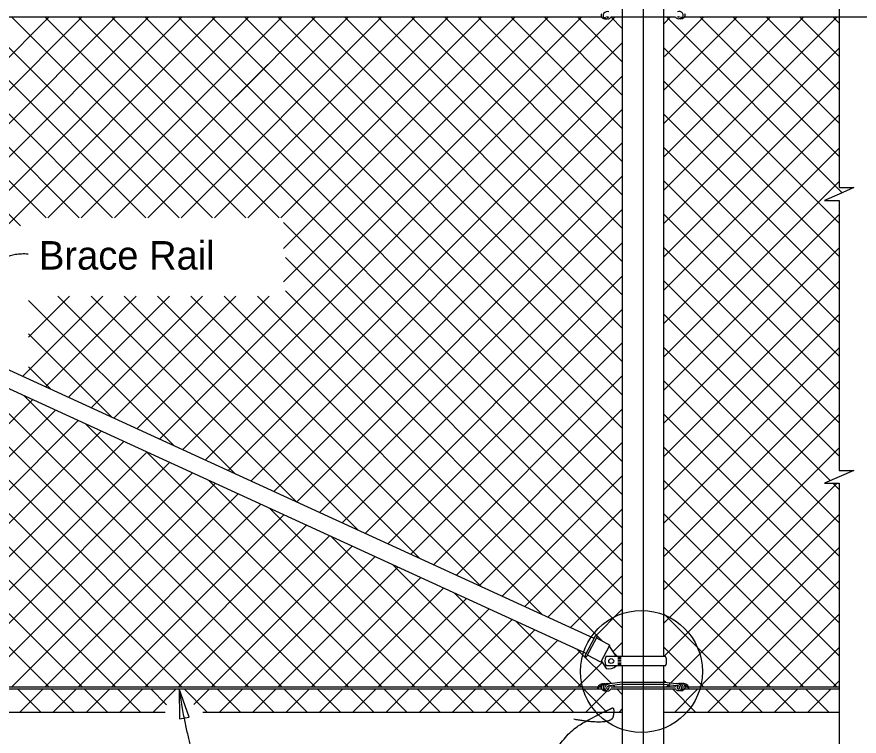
# Model space of a CAD drawing. Extents: x 0 to 41.1, y 0 to 26.4.
# Drawn here: x 17.77 to 23.73, y 17.3 to 22.39 of the extents above; entities that cross this region are included whole.
import ezdxf

# ---------------------------------------------------------------- set-up
doc = ezdxf.new("R2010")
doc.units = 0
for name, color, linetype in [('CL_Major', 7, 'Continuous'), ('Dimension', 7, 'Continuous'), ('Miscellaneous', 7, 'Continuous'), ('SteelMisc', 7, 'Continuous'), ('SteelMisc_h', 7, 'Continuous'), ('SupstrConc', 7, 'Continuous'), ('TextStructures', 7, 'Continuous')]:
    doc.layers.add(name, color=color, linetype=linetype)

msp = doc.modelspace()

# ---------------------------------------------------------------- linework, layer by layer
at = {"layer": 'CL_Major'}
msp.add_line((22.2062, 25.6784), (22.2062, 14.8312), dxfattribs=at)
at = {"layer": 'Dimension'}
for points in [[(23.5932, 24.349), (23.5932, 21.1819), (23.6966, 21.1819), (23.5932, 21.1369), (23.4899, 21.0919), (23.5932, 21.0919), (23.5932, 20.1983)], [(23.5932, 20.1983), (23.5932, 19.1806), (23.6966, 19.1806), (23.5932, 19.1356), (23.4899, 19.0906), (23.5932, 19.0906), (23.5932, 16.8862)]]:
    msp.add_lwpolyline(points, dxfattribs=at)
msp.add_lwpolyline([(18.9209, 17.6338), (18.9225, 17.4226), (18.992, 17.4349)], close=True, dxfattribs=at)
msp.add_circle((22.1934, 17.7574), 0.4318, dxfattribs=at)
for points in [[(17.8509, 20.7118), (17.6943, 20.72), (17.5763, 20.5615), (17.5733, 20.4403), (17.578, 20.2726), (17.6407, 19.9238)], [(18.6095, 16.8868), (18.8324, 16.8833), (18.9173, 16.9222), (19.0482, 17.0709), (18.9633, 17.3684), (18.9208, 17.6337)], [(20.4632, 14.9843), (21.3717, 14.9643), (21.3652, 16.4454), (21.4405, 16.9433), (21.6515, 17.3204), (21.8903, 17.4554), (21.9647, 17.4872), (22.0043, 17.5089), (21.982, 17.3708), (21.7151, 17.4193)]]:
    msp.add_open_spline(points, degree=2, dxfattribs=at)
at = {"layer": 'Miscellaneous'}
for p, q in [((16.1953, 20.586), (17.9993, 22.39)), ((16.32, 22.39), (17.7983, 20.9117)), ((16.357, 20.5119), (18.235, 22.39)), ((16.5186, 20.4379), (18.4707, 22.39)), ((16.5557, 22.39), (17.9778, 20.9679)), ((16.6803, 20.3639), (18.7064, 22.39)), ((16.7914, 22.39), (18.2135, 20.9679)), ((16.8419, 20.2898), (18.9421, 22.39)), ((17.0271, 22.39), (18.4492, 20.9679)), ((17.2628, 22.39), (18.6849, 20.9679)), ((17.4985, 22.39), (18.9206, 20.9679)), ((17.679, 20.8912), (19.1778, 22.39)), ((17.7342, 22.39), (19.1563, 20.9679)), ((17.9699, 22.39), (19.392, 20.9679)), ((17.9914, 20.9679), (19.4135, 22.39)), ((18.2056, 22.39), (19.6277, 20.9679)), ((18.2272, 20.9679), (19.6492, 22.39)), ((18.4413, 22.39), (22.0604, 18.7709)), ((18.677, 22.39), (22.0604, 19.0066)), ((18.6986, 20.9679), (20.1206, 22.39)), ((18.7818, 19.4013), (21.7706, 22.39)), ((18.9127, 22.39), (22.0604, 19.2423)), ((18.9343, 20.9679), (20.3563, 22.39)), ((18.9435, 19.3272), (22.0063, 22.39)), ((19.1484, 22.39), (22.0604, 19.478)), ((19.17, 20.9679), (20.5921, 22.39)), ((19.3184, 21.8234), (19.8849, 22.39)), ((19.3841, 22.39), (22.0604, 19.7137)), ((19.4057, 20.9679), (20.8278, 22.39)), ((19.6198, 22.39), (22.0604, 19.9494)), ((19.6414, 20.9679), (21.0635, 22.39)), ((19.66, 20.7508), (21.2992, 22.39)), ((19.66, 20.5151), (21.5349, 22.39)), ((19.8555, 22.39), (22.0604, 20.1851)), ((20.0912, 22.39), (22.0604, 20.4208)), ((20.3269, 22.39), (22.0604, 20.6565)), ((20.5626, 22.39), (22.0604, 20.8922)), ((20.7983, 22.39), (22.0604, 21.1279)), ((21.034, 22.39), (22.0604, 21.3636)), ((21.2697, 22.39), (22.0604, 21.5993)), ((21.5054, 22.39), (22.0604, 21.835)), ((21.7411, 22.39), (22.0604, 22.0707)), ((21.9768, 22.39), (22.0604, 22.3064)), ((22.3521, 21.3996), (23.3424, 22.39)), ((22.3521, 21.6353), (23.1067, 22.39)), ((22.3521, 21.1639), (23.5781, 22.39)), ((22.3521, 21.871), (22.871, 22.39)), ((22.3521, 22.3424), (22.3996, 22.39)), ((22.3565, 22.1112), (22.6353, 22.39)), ((22.3702, 22.39), (23.6142, 21.146)), ((22.6059, 22.39), (23.5931, 21.4028)), ((22.8416, 22.39), (23.5931, 21.6385)), ((23.0773, 22.39), (23.5931, 21.8742)), ((23.313, 22.39), (23.5931, 22.1099)), ((23.5487, 22.39), (23.5931, 22.3456)), ((19.1051, 19.2532), (22.0604, 22.2084)), ((22.3521, 22.1725), (23.5931, 20.9314)), ((22.3521, 20.9282), (23.5931, 22.1693)), ((18.4629, 20.9679), (19.5478, 22.0528)), ((19.2668, 19.1791), (22.0604, 21.9727)), ((22.3521, 21.9368), (23.5931, 20.6957)), ((22.3521, 20.6925), (23.5931, 21.9336)), ((19.4285, 19.1051), (22.0604, 21.737)), ((22.3521, 21.701), (23.5931, 20.46)), ((22.3521, 20.4568), (23.5931, 21.6979)), ((19.5901, 19.0311), (22.0604, 21.5013)), ((22.3521, 21.4653), (23.5931, 20.2243)), ((22.3521, 20.2211), (23.5931, 21.4622)), ((19.7518, 18.957), (22.0604, 21.2656)), ((22.3521, 21.2296), (23.5931, 19.9886)), ((22.3521, 19.9854), (23.5931, 21.2265)), ((19.9134, 18.883), (22.0604, 21.0299)), ((22.3521, 20.9939), (23.5931, 19.7529)), ((19.66, 20.9356), (22.0604, 18.5352)), ((22.3521, 19.7497), (23.5931, 20.9908)), ((15.2134, 20.9039), (18.4687, 17.6486)), ((20.0751, 18.8089), (22.0604, 20.7942)), ((22.3521, 20.7582), (23.5931, 19.5171)), ((22.3521, 19.514), (23.5931, 20.7551)), ((15.6483, 20.7047), (18.7044, 17.6486)), ((19.6731, 20.6868), (22.0604, 18.2995)), ((20.2368, 18.7349), (22.0604, 20.5585)), ((22.3521, 20.5225), (23.5931, 19.2814)), ((22.3521, 19.2783), (23.5931, 20.5194)), ((16.0832, 20.5055), (18.9401, 17.6486)), ((17.8119, 19.8455), (18.3797, 20.4134)), ((17.8545, 20.1239), (18.144, 20.4134)), ((17.9735, 19.7715), (18.6154, 20.4134)), ((18.0609, 20.4134), (19.3191, 19.1552)), ((18.1352, 19.6975), (18.8511, 20.4134)), ((18.2966, 20.4134), (19.754, 18.956)), ((18.2969, 19.6234), (19.0868, 20.4134)), ((18.4585, 19.5494), (19.3225, 20.4134)), ((18.5323, 20.4134), (20.1889, 18.7568)), ((18.6202, 19.4753), (19.5582, 20.4134)), ((18.768, 20.4134), (20.6238, 18.5576)), ((19.0037, 20.4134), (21.0587, 18.3584)), ((19.2394, 20.4134), (21.4936, 18.1592)), ((19.4751, 20.4134), (21.9144, 17.9741)), ((19.6731, 20.4511), (22.0604, 18.0638)), ((17.8545, 20.3841), (18.8842, 19.3544)), ((16.5181, 20.3063), (19.1758, 17.6486)), ((20.3984, 18.6608), (22.0604, 20.3228)), ((22.3521, 20.2868), (23.5306, 19.1083)), ((22.3521, 19.0426), (23.5931, 20.2837)), ((16.953, 20.1071), (19.4115, 17.6486)), ((17.8545, 20.1484), (18.4493, 19.5536)), ((20.5601, 18.5868), (22.0604, 20.0871)), ((22.3521, 20.0511), (23.5931, 18.81)), ((22.3521, 18.8069), (23.5931, 20.048)), ((17.3879, 19.9079), (19.6472, 17.6486)), ((17.8545, 19.9127), (18.0144, 19.7528)), ((20.7217, 18.5127), (22.0604, 19.8514)), ((22.3521, 19.8154), (23.5931, 18.5743)), ((22.3521, 18.5712), (23.5931, 19.8123)), ((16.6339, 18.4318), (17.8831, 19.6811)), ((17.8228, 19.7087), (19.8829, 17.6486)), ((16.2952, 19.5864), (18.233, 17.6486)), ((16.6339, 18.1961), (18.0448, 19.607)), ((20.8834, 18.4387), (22.0604, 19.6157)), ((22.3521, 19.5797), (23.5931, 18.3386)), ((22.3521, 18.3355), (23.5931, 19.5766)), ((16.6339, 17.9604), (18.2064, 19.533)), ((18.2576, 19.5095), (20.1186, 17.6486)), ((16.5577, 17.6486), (18.3681, 19.4589)), ((16.2349, 19.4109), (17.9973, 17.6486)), ((16.7934, 17.6486), (18.5298, 19.3849)), ((21.045, 18.3647), (22.0604, 19.38)), ((22.3521, 19.344), (23.5931, 18.1029)), ((22.3521, 18.0998), (23.5931, 19.3409)), ((17.0291, 17.6486), (18.6914, 19.3109)), ((18.6925, 19.3103), (20.3543, 17.6486)), ((17.2648, 17.6486), (18.8531, 19.2368)), ((17.5005, 17.6486), (19.0147, 19.1628)), ((21.2067, 18.2906), (22.0604, 19.1443)), ((17.7362, 17.6486), (19.1764, 19.0887)), ((19.1274, 19.1111), (20.59, 17.6486)), ((22.3521, 19.1083), (23.5931, 17.8672)), ((22.3521, 17.8641), (23.5785, 19.0905)), ((23.5484, 19.0905), (23.5931, 19.0457)), ((17.9719, 17.6486), (19.338, 19.0147)), ((18.2076, 17.6486), (19.4997, 18.9406)), ((19.5623, 18.912), (20.8257, 17.6486)), ((21.3684, 18.2166), (22.0604, 18.9086)), ((18.4433, 17.6486), (19.6614, 18.8666)), ((22.3521, 18.8726), (23.5761, 17.6486)), ((22.4004, 17.6767), (23.5931, 18.8695)), ((18.679, 17.6486), (19.823, 18.7926)), ((18.9147, 17.6486), (19.9847, 18.7185)), ((19.9972, 18.7128), (21.0614, 17.6486)), ((21.53, 18.1425), (22.0604, 18.6729)), ((19.1504, 17.6486), (20.1463, 18.6445)), ((22.3521, 18.6369), (23.3404, 17.6486)), ((22.6079, 17.6486), (23.5931, 18.6338)), ((19.3861, 17.6486), (20.308, 18.5704)), ((19.6218, 17.6486), (20.4697, 18.4964)), ((20.4321, 18.5136), (21.2971, 17.6486)), ((21.6917, 18.0685), (22.0604, 18.4372)), ((19.8575, 17.6486), (20.6313, 18.4223)), ((22.3521, 18.4012), (23.1047, 17.6486)), ((22.8436, 17.6486), (23.5931, 18.3981)), ((20.0932, 17.6486), (20.793, 18.3483)), ((20.867, 18.3144), (21.5328, 17.6486)), ((20.3289, 17.6486), (20.9546, 18.2742)), ((20.5646, 17.6486), (21.1163, 18.2002)), ((21.8533, 17.9944), (22.0604, 18.2015)), ((22.3521, 18.1655), (22.869, 17.6486)), ((23.0793, 17.6486), (23.5931, 18.1624)), ((20.8003, 17.6486), (21.278, 18.1262)), ((21.3019, 18.1152), (21.7685, 17.6486)), ((21.0361, 17.6486), (21.4396, 18.0521)), ((21.2718, 17.6486), (21.6013, 17.9781)), ((21.9916, 17.897), (22.0604, 17.9658)), ((21.5075, 17.6486), (21.7629, 17.904)), ((21.7368, 17.916), (21.9815, 17.6713)), ((21.9917, 17.8968), (22.0239, 17.8646)), ((22.3521, 17.9298), (22.6333, 17.6486)), ((23.315, 17.6486), (23.5931, 17.9267)), ((21.7432, 17.6486), (21.9158, 17.8212)), ((21.8835, 17.6486), (21.8871, 17.6521)), ((21.9931, 17.6597), (22.0042, 17.6486)), ((22.3521, 17.6941), (22.365, 17.6812)), ((22.3722, 17.6486), (22.3882, 17.6645)), ((22.3809, 17.6653), (22.3976, 17.6486)), ((22.3929, 17.6692), (22.397, 17.6733)), ((23.5507, 17.6486), (23.5931, 17.691)), ((17.7763, 17.6338), (17.9408, 17.4693)), ((17.7927, 17.4693), (17.9572, 17.6338)), ((18.012, 17.6338), (18.1765, 17.4693)), ((18.0284, 17.4693), (18.1929, 17.6338)), ((18.2478, 17.6338), (18.4122, 17.4693)), ((18.2641, 17.4693), (18.4286, 17.6338)), ((18.4835, 17.6338), (18.6479, 17.4693)), ((18.4998, 17.4693), (18.6643, 17.6338)), ((18.7192, 17.6338), (18.8307, 17.5223)), ((18.7355, 17.4693), (18.9, 17.6338)), ((18.9549, 17.6338), (19.1193, 17.4693)), ((19.0244, 17.5226), (19.1357, 17.6338)), ((19.1906, 17.6338), (19.355, 17.4693)), ((19.2069, 17.4693), (19.3714, 17.6338)), ((19.4263, 17.6338), (19.5907, 17.4693)), ((19.4426, 17.4693), (19.6071, 17.6338)), ((19.662, 17.6338), (19.8264, 17.4693)), ((19.6783, 17.4693), (19.8428, 17.6338)), ((19.8977, 17.6338), (20.0621, 17.4693)), ((19.914, 17.4693), (20.0785, 17.6338)), ((20.1334, 17.6338), (20.2978, 17.4693)), ((20.1497, 17.4693), (20.3142, 17.6338)), ((20.3691, 17.6338), (20.5336, 17.4693)), ((20.3854, 17.4693), (20.5499, 17.6338)), ((20.6048, 17.6338), (20.7693, 17.4693)), ((20.6211, 17.4693), (20.7856, 17.6338)), ((20.8405, 17.6338), (21.005, 17.4693)), ((20.8568, 17.4693), (21.0213, 17.6338)), ((21.0762, 17.6338), (21.2407, 17.4693)), ((21.0925, 17.4693), (21.257, 17.6338)), ((21.3119, 17.6338), (21.4764, 17.4693)), ((21.3282, 17.4693), (21.4927, 17.6338)), ((21.5476, 17.6338), (21.7121, 17.4693)), ((21.5639, 17.4693), (21.7284, 17.6338)), ((21.7833, 17.6338), (21.9478, 17.4693)), ((21.7996, 17.4693), (21.9506, 17.6203)), ((22.019, 17.6338), (22.0604, 17.5924)), ((22.3521, 17.6284), (22.3575, 17.6338)), ((22.4124, 17.6338), (22.5768, 17.4693)), ((22.4287, 17.4693), (22.5932, 17.6338)), ((22.6481, 17.6338), (22.8125, 17.4693)), ((22.6644, 17.4693), (22.8289, 17.6338)), ((22.8838, 17.6338), (23.0482, 17.4693)), ((22.9001, 17.4693), (23.0646, 17.6338)), ((23.1195, 17.6338), (23.2839, 17.4693)), ((23.1358, 17.4693), (23.3003, 17.6338)), ((23.3552, 17.6338), (23.5196, 17.4693)), ((23.3715, 17.4693), (23.536, 17.6338)), ((23.5909, 17.6338), (23.5931, 17.6315)), ((22.0353, 17.4693), (22.0604, 17.4944))]:
    msp.add_line(p, q, dxfattribs=at)
at = {"layer": 'SteelMisc'}
for p, q in [((22.0604, 17.8646), (22.0604, 24.349)), ((22.3521, 17.8646), (22.3521, 24.349)), ((12.4978, 22.39), (21.9118, 22.39)), ((21.9767, 22.39), (22.0603, 22.39)), ((22.352, 22.39), (22.4351, 22.39)), ((22.4978, 22.39), (25.9375, 22.39)), ((21.8588, 17.9919), (12.6088, 22.2288)), ((21.8028, 17.8858), (12.5526, 22.1225)), ((21.7953, 17.8717), (21.8678, 18.0088)), ((21.8072, 17.8654), (21.8796, 18.0026)), ((21.8755, 17.9947), (21.9698, 17.9448)), ((21.9061, 17.8242), (21.9698, 17.9448)), ((21.9656, 17.9368), (22.0124, 17.8651)), ((21.9061, 17.8242), (21.8118, 17.8741)), ((21.9095, 17.8308), (21.9443, 17.7777)), ((22.3634, 17.8646), (21.9436, 17.8646)), ((22.026, 17.8584), (22.0495, 17.8584)), ((22.026, 17.8486), (22.0495, 17.8486)), ((22.026, 17.8368), (22.0495, 17.8368)), ((22.3633, 17.7968), (21.9436, 17.7968)), ((22.026, 17.825), (22.0495, 17.825)), ((22.026, 17.8142), (22.0495, 17.8142)), ((22.026, 17.8046), (22.0495, 17.8046)), ((22.0604, 17.0944), (22.0604, 17.7968)), ((22.3521, 17.0944), (22.3521, 17.7968)), ((22.0604, 17.6812), (21.9675, 17.6695)), ((22.0604, 17.6667), (21.9676, 17.657)), ((22.0604, 17.6812), (22.3516, 17.6829)), ((22.0604, 17.6667), (22.3516, 17.6683)), ((22.3516, 17.6829), (22.4435, 17.6713)), ((22.3516, 17.6683), (22.4434, 17.6588)), ((12.5141, 17.6338), (21.9119, 17.6338)), ((12.5154, 17.6486), (21.8852, 17.6486)), ((21.8952, 17.6486), (21.9083, 17.6486)), ((21.9768, 17.6338), (22.0604, 17.6338)), ((21.9782, 17.6486), (22.0604, 17.6486)), ((22.3521, 17.6486), (22.4325, 17.6486)), ((22.3521, 17.6338), (22.4351, 17.6338)), ((22.4979, 17.6338), (23.5931, 17.6338)), ((22.5028, 17.6486), (22.518, 17.6486)), ((22.5265, 17.6486), (23.5931, 17.6486))]:
    msp.add_line(p, q, dxfattribs=at)
for centre, start, end in [((21.8739, 18.0058), 332.14902, 152.14902), ((21.8014, 17.8686), 152.14902, 332.14902)]:
    msp.add_arc(centre, 0.00673, start, end, dxfattribs=at)
for centre, major_axis, ratio, start_param, end_param in [((21.9507, 22.3996), (0.0295, 0), 0.957868, 1.132635, 3.996184), ((22.4603, 22.4014), (-0.0295, 0), 0.957868, 2.287002, 5.15055), ((21.9331, 22.4025), (-0.0249, 0), 0.957868, 5.913851, 7.104804), ((21.9344, 22.3985), (0.0231, 0), 0.957868, 3.795406, 4.839145), ((21.9405, 22.3928), (0.0206, -0.0021), 0.798607, 4.329004, 5.170153), ((21.954, 22.3928), (0.0206, -0.0021), 0.798607, 3.319436, 5.220153), ((21.9552, 22.3949), (-0.00795, 0), 0.957868, 0.039428, 2.999692), ((21.9466, 22.4115), (0.0391, 0), 0.957868, 5.134108, 5.41974), ((21.9537, 22.3995), (0.0251, 0), 0.957868, 5.531357, 5.877802), ((22.4572, 22.4013), (-0.0251, 0), 0.957868, 0.487549, 0.751829), ((22.4643, 22.4133), (-0.0391, 0), 0.957868, 0.863445, 1.149078), ((22.4558, 22.3967), (0.00795, 0), 0.957868, 3.283494, 6.243757), ((22.4569, 22.3945), (-0.0206, -0.0021), 0.798607, 1.063032, 2.96375), ((22.4704, 22.3945), (-0.0206, -0.0021), 0.798607, 1.113032, 1.956656), ((22.4765, 22.4002), (-0.0231, 0), 0.957868, 1.44404, 2.503632), ((22.4779, 22.4042), (0.0249, 0), 0.957868, 5.476514, 6.65252), ((22.0129, 17.8309), (-0.0776, 0), 0.957868, 5.810211, 6.75616), ((22.2943, 17.8309), (0.0776, 0), 0.957868, 5.807767, 6.754779), ((21.9609, 17.846), (0.0647, -0.0342), 0.957868, 4.95193, 6.011789), ((21.9195, 17.6343), (0.0373, 0), 0.957868, 1.427863, 3.108042), ((21.9406, 17.5946), (-0.0724, 0), 0.957868, 5.133134, 5.652106), ((21.9331, 17.6463), (-0.0249, 0), 0.957868, 5.913851, 7.104804), ((21.932, 17.6488), (0.023, 0), 0.957868, 1.234085, 2.861055), ((21.9507, 17.6434), (0.0295, 0), 0.957868, 1.132635, 3.996184), ((21.9642, 17.6452), (-0.0303, -0.0108), 0.724765, 4.35367, 6.224248), ((21.9693, 17.6323), (-0.0259, 0), 0.957868, 4.777514, 5.646371), ((21.9535, 17.6445), (0.0119, 0), 0.957868, 5.725876, 7.416677), ((21.9538, 17.6433), (0.0251, 0), 0.957868, 0.221743, 0.642584), ((22.4573, 17.6451), (-0.0251, 0), 0.957868, 5.640694, 6.136824), ((22.4418, 17.634), (0.0259, 0), 0.957868, 0.636815, 1.505671), ((22.4468, 17.647), (0.0303, -0.0108), 0.724765, 0.058937, 1.929515), ((22.4575, 17.6463), (-0.0119, 0), 0.957868, 5.149694, 6.840495), ((22.4603, 17.6452), (-0.0295, 0), 0.957868, 2.287002, 5.15055), ((22.479, 17.6505), (-0.023, 0), 0.957868, 3.422131, 5.0491), ((22.4915, 17.6361), (-0.0373, 0), 0.957868, 3.175144, 4.855322), ((22.4779, 17.648), (0.0249, 0), 0.957868, 5.461566, 6.65252), ((22.4704, 17.5964), (0.0724, 0), 0.957868, 0.631079, 1.150052), ((21.9345, 17.6423), (0.0231, 0), 0.957868, 3.795406, 4.839145), ((21.9406, 17.6366), (0.0206, -0.0021), 0.798607, 4.32653, 5.170153), ((21.9541, 17.6366), (0.0206, -0.0021), 0.798607, 3.319436, 5.220153), ((21.9609, 17.6411), (-0.0139, 0), 0.957868, 5.822914, 6.485782), ((21.9552, 17.6387), (-0.00795, 0), 0.957868, 0.039428, 2.999692), ((21.9467, 17.6553), (0.0391, 0), 0.957868, 5.134108, 5.41974), ((21.9535, 17.6445), (0.0119, 0), 0.957868, 5.639684, 5.725876), ((21.9538, 17.6433), (0.0251, 0), 0.957868, 5.531357, 5.877802), ((22.4573, 17.6451), (-0.0251, 0), 0.957868, 0.487549, 0.751829), ((22.4643, 17.6571), (-0.0391, 0), 0.957868, 0.863445, 1.149078), ((22.4575, 17.6463), (-0.0119, 0), 0.957868, 0.557309, 0.643501), ((22.4558, 17.6405), (0.00795, 0), 0.957868, 3.283494, 6.243757), ((22.4569, 17.6383), (-0.0206, -0.0021), 0.798607, 1.063032, 2.96375), ((22.4501, 17.6429), (0.0139, 0), 0.957868, 6.080589, 6.743456), ((22.4704, 17.6383), (-0.0206, -0.0021), 0.798607, 1.113032, 1.956656), ((22.4765, 17.644), (-0.0231, 0), 0.957868, 1.44404, 2.487779)]:
    msp.add_ellipse(centre, major_axis=major_axis, ratio=ratio, start_param=start_param, end_param=end_param, dxfattribs=at)
msp.add_ellipse((21.9795, 17.8313), major_axis=(0.0178, 0), ratio=0.957868, dxfattribs=at)
at = {"layer": 'SteelMisc_h'}
for p, q in [((22.0603, 22.39), (22.352, 22.39)), ((22.0604, 17.6486), (22.3521, 17.6486)), ((22.0604, 17.6338), (22.3521, 17.6338))]:
    msp.add_line(p, q, dxfattribs=at)
at = {"layer": 'SupstrConc'}
for p, q in [((12.3521, 17.4693), (18.8204, 17.4693)), ((19.0892, 17.4693), (22.0604, 17.4693)), ((22.3521, 17.4693), (23.5931, 17.4693))]:
    msp.add_line(p, q, dxfattribs=at)

# ---------------------------------------------------------------- texts
at = {"layer": 'TextStructures'}
msp.add_text('Brace Rail', height=0.2016, dxfattribs=at).set_placement((17.9282, 20.6019))

doc.saveas('drawing.dxf')
